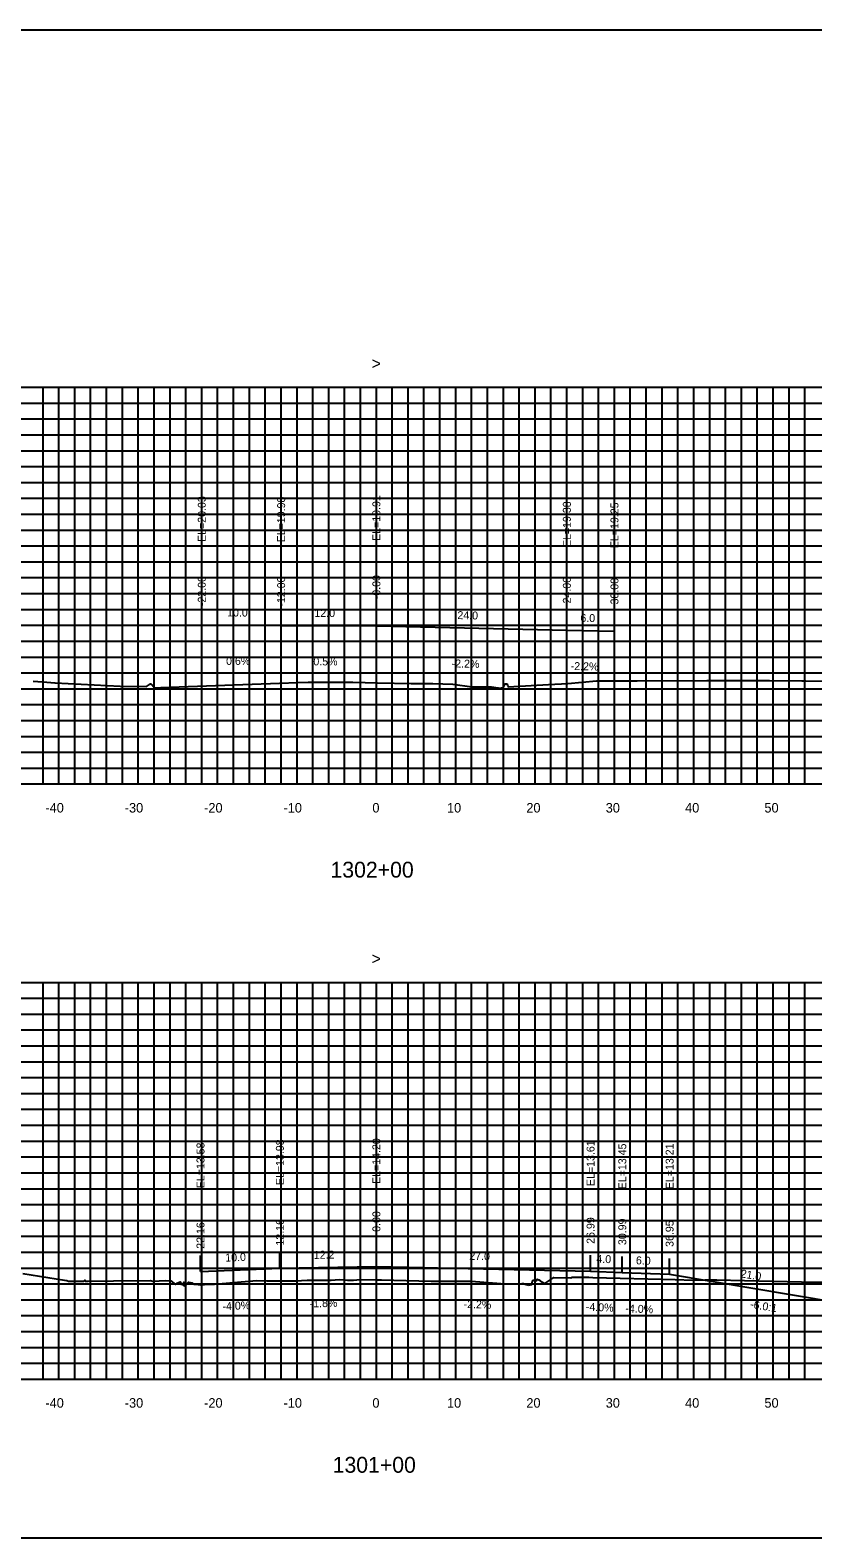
# Model space of a CAD drawing. Extents: x 1797714 to 1804825, y 249015 to 250269.
# Drawn here: x 1802560.5 to 1802659.2, y 249628.2 to 249818.2 of the extents above; entities that cross this region are included whole.
import ezdxf

# ---------------------------------------------------------------- set-up
doc = ezdxf.new("R2010")
doc.units = 0
for name, color, linetype in [('1', 7, 'Continuous'), ('10', 7, 'Continuous'), ('3', 7, 'Continuous'), ('4', 7, 'Continuous'), ('60', 7, 'Continuous'), ('CL-CNST', 7, 'Continuous'), ('Level 62', 7, 'Continuous'), ('M-ROADS', 7, 'Continuous')]:
    doc.layers.add(name, color=color, linetype=linetype)

msp = doc.modelspace()

# ---------------------------------------------------------------- linework, layer by layer
for p, q in [((1802582.16, 249743.2), (1802582.16, 249745.2)), ((1802592.16, 249743.14), (1802592.16, 249745.14)), ((1802604.16, 249743.08), (1802604.16, 249745.08)), ((1802628.16, 249742.55), (1802628.16, 249744.55)), ((1802634.16, 249742.42), (1802634.16, 249744.42)), ((1802592, 249662.14), (1802592, 249664.14)), ((1802604.16, 249662.37), (1802604.16, 249664.37)), ((1802582, 249661.74), (1802582, 249663.74)), ((1802631.15, 249661.77), (1802631.15, 249663.77)), ((1802635.15, 249661.61), (1802635.15, 249663.61)), ((1802641.11, 249661.38), (1802641.11, 249663.38))]:
    msp.add_line(p, q)
msp.add_lwpolyline([(1802454.16, 249628.17), (1802754.16, 249628.17), (1802754.16, 249818.17), (1802454.16, 249818.17)], close=True)
at = {"layer": '60'}
for p, q in [((1802454.16, 249723.17), (1802754.16, 249723.17)), ((1802564.16, 249723.11), (1802564.16, 249723.17)), ((1802574.16, 249723.11), (1802574.16, 249723.17)), ((1802584.16, 249723.11), (1802584.16, 249723.17)), ((1802594.16, 249723.11), (1802594.16, 249723.17)), ((1802604.16, 249723.11), (1802604.16, 249723.17)), ((1802614.16, 249723.11), (1802614.16, 249723.17)), ((1802624.16, 249723.11), (1802624.16, 249723.17)), ((1802634.16, 249723.11), (1802634.16, 249723.17)), ((1802644.16, 249723.11), (1802644.16, 249723.17)), ((1802654.16, 249723.11), (1802654.16, 249723.17)), ((1802454.16, 249648.17), (1802754.16, 249648.17)), ((1802564.16, 249648.11), (1802564.16, 249648.17)), ((1802574.16, 249648.11), (1802574.16, 249648.17)), ((1802584.16, 249648.11), (1802584.16, 249648.17)), ((1802594.16, 249648.11), (1802594.16, 249648.17)), ((1802604.16, 249648.11), (1802604.16, 249648.17)), ((1802614.16, 249648.11), (1802614.16, 249648.17)), ((1802624.16, 249648.11), (1802624.16, 249648.17)), ((1802634.16, 249648.11), (1802634.16, 249648.17)), ((1802644.16, 249648.11), (1802644.16, 249648.17)), ((1802654.16, 249648.11), (1802654.16, 249648.17))]:
    msp.add_line(p, q, dxfattribs=at)
at = {"layer": 'CL-CNST'}
for points in [[(1802582.16, 249743.2), (1802592.16, 249743.14), (1802604.16, 249743.08), (1802628.16, 249742.55), (1802634.16, 249742.42)], [(1802582, 249661.74), (1802592, 249662.14), (1802604.16, 249662.37), (1802631.15, 249661.77), (1802635.15, 249661.61), (1802641.11, 249661.38), (1802662.11, 249657.88), (1802666.11, 249657.88), (1802676.28, 249660.42)]]:
    msp.add_lwpolyline(points, dxfattribs=at)
at = {"layer": 'Level 62'}
for p, q in [((1802454.16, 249773.17), (1802754.16, 249773.17)), ((1802562.16, 249723.17), (1802562.16, 249773.17)), ((1802564.16, 249723.17), (1802564.16, 249773.17)), ((1802566.16, 249723.17), (1802566.16, 249773.17)), ((1802568.16, 249723.17), (1802568.16, 249773.17)), ((1802570.16, 249723.17), (1802570.16, 249773.17)), ((1802572.16, 249723.17), (1802572.16, 249773.17)), ((1802574.16, 249723.17), (1802574.16, 249773.17)), ((1802576.16, 249723.17), (1802576.16, 249773.17)), ((1802578.16, 249723.17), (1802578.16, 249773.17)), ((1802580.16, 249723.17), (1802580.16, 249773.17)), ((1802582.16, 249723.17), (1802582.16, 249773.17)), ((1802584.16, 249723.17), (1802584.16, 249773.17)), ((1802586.16, 249723.17), (1802586.16, 249773.17)), ((1802588.16, 249723.17), (1802588.16, 249773.17)), ((1802590.16, 249723.17), (1802590.16, 249773.17)), ((1802592.16, 249723.17), (1802592.16, 249773.17)), ((1802594.16, 249723.17), (1802594.16, 249773.17)), ((1802596.16, 249723.17), (1802596.16, 249773.17)), ((1802598.16, 249723.17), (1802598.16, 249773.17)), ((1802600.16, 249723.17), (1802600.16, 249773.17)), ((1802602.16, 249723.17), (1802602.16, 249773.17)), ((1802604.16, 249723.17), (1802604.16, 249773.17)), ((1802606.16, 249723.17), (1802606.16, 249773.17)), ((1802608.16, 249723.17), (1802608.16, 249773.17)), ((1802610.16, 249723.17), (1802610.16, 249773.17)), ((1802612.16, 249723.17), (1802612.16, 249773.17)), ((1802614.16, 249723.17), (1802614.16, 249773.17)), ((1802616.16, 249723.17), (1802616.16, 249773.17)), ((1802618.16, 249723.17), (1802618.16, 249773.17)), ((1802620.16, 249723.17), (1802620.16, 249773.17)), ((1802622.16, 249723.17), (1802622.16, 249773.17)), ((1802624.16, 249723.17), (1802624.16, 249773.17)), ((1802626.16, 249723.17), (1802626.16, 249773.17)), ((1802628.16, 249723.17), (1802628.16, 249773.17)), ((1802630.16, 249723.17), (1802630.16, 249773.17)), ((1802632.16, 249723.17), (1802632.16, 249773.17)), ((1802634.16, 249723.17), (1802634.16, 249773.17)), ((1802636.16, 249723.17), (1802636.16, 249773.17)), ((1802638.16, 249723.17), (1802638.16, 249773.17)), ((1802640.16, 249723.17), (1802640.16, 249773.17)), ((1802642.16, 249723.17), (1802642.16, 249773.17)), ((1802644.16, 249723.17), (1802644.16, 249773.17)), ((1802646.16, 249723.17), (1802646.16, 249773.17)), ((1802648.16, 249723.17), (1802648.16, 249773.17)), ((1802650.16, 249723.17), (1802650.16, 249773.17)), ((1802652.16, 249723.17), (1802652.16, 249773.17)), ((1802654.16, 249723.17), (1802654.16, 249773.17)), ((1802656.16, 249723.17), (1802656.16, 249773.17)), ((1802658.16, 249723.17), (1802658.16, 249773.17)), ((1802454.16, 249771.17), (1802754.16, 249771.17)), ((1802454.16, 249769.17), (1802754.16, 249769.17)), ((1802454.16, 249767.17), (1802754.16, 249767.17)), ((1802454.16, 249765.17), (1802754.16, 249765.17)), ((1802454.16, 249763.17), (1802754.16, 249763.17)), ((1802454.16, 249761.17), (1802754.16, 249761.17)), ((1802454.16, 249759.17), (1802754.16, 249759.17)), ((1802454.16, 249757.17), (1802754.16, 249757.17)), ((1802454.16, 249755.17), (1802754.16, 249755.17)), ((1802454.16, 249753.17), (1802754.16, 249753.17)), ((1802454.16, 249751.17), (1802754.16, 249751.17)), ((1802454.16, 249749.17), (1802754.16, 249749.17)), ((1802454.16, 249747.17), (1802754.16, 249747.17)), ((1802454.16, 249745.17), (1802754.16, 249745.17)), ((1802454.16, 249743.17), (1802754.16, 249743.17)), ((1802454.16, 249741.17), (1802754.16, 249741.17)), ((1802454.16, 249739.17), (1802754.16, 249739.17)), ((1802454.16, 249737.17), (1802754.16, 249737.17)), ((1802454.16, 249735.17), (1802754.16, 249735.17)), ((1802454.16, 249733.17), (1802754.16, 249733.17)), ((1802454.16, 249731.17), (1802754.16, 249731.17)), ((1802454.16, 249729.17), (1802754.16, 249729.17)), ((1802454.16, 249727.17), (1802754.16, 249727.17)), ((1802454.16, 249725.17), (1802754.16, 249725.17)), ((1802454.16, 249723.17), (1802754.16, 249723.17)), ((1802454.16, 249698.17), (1802754.16, 249698.17)), ((1802562.16, 249648.17), (1802562.16, 249698.17)), ((1802564.16, 249648.17), (1802564.16, 249698.17)), ((1802566.16, 249648.17), (1802566.16, 249698.17)), ((1802568.16, 249648.17), (1802568.16, 249698.17)), ((1802570.16, 249648.17), (1802570.16, 249698.17)), ((1802572.16, 249648.17), (1802572.16, 249698.17)), ((1802574.16, 249648.17), (1802574.16, 249698.17)), ((1802576.16, 249648.17), (1802576.16, 249698.17)), ((1802578.16, 249648.17), (1802578.16, 249698.17)), ((1802580.16, 249648.17), (1802580.16, 249698.17)), ((1802582.16, 249648.17), (1802582.16, 249698.17)), ((1802584.16, 249648.17), (1802584.16, 249698.17)), ((1802586.16, 249648.17), (1802586.16, 249698.17)), ((1802588.16, 249648.17), (1802588.16, 249698.17)), ((1802590.16, 249648.17), (1802590.16, 249698.17)), ((1802592.16, 249648.17), (1802592.16, 249698.17)), ((1802594.16, 249648.17), (1802594.16, 249698.17)), ((1802596.16, 249648.17), (1802596.16, 249698.17)), ((1802598.16, 249648.17), (1802598.16, 249698.17)), ((1802600.16, 249648.17), (1802600.16, 249698.17)), ((1802602.16, 249648.17), (1802602.16, 249698.17)), ((1802604.16, 249648.17), (1802604.16, 249698.17)), ((1802606.16, 249648.17), (1802606.16, 249698.17)), ((1802608.16, 249648.17), (1802608.16, 249698.17)), ((1802610.16, 249648.17), (1802610.16, 249698.17)), ((1802612.16, 249648.17), (1802612.16, 249698.17)), ((1802614.16, 249648.17), (1802614.16, 249698.17)), ((1802616.16, 249648.17), (1802616.16, 249698.17)), ((1802618.16, 249648.17), (1802618.16, 249698.17)), ((1802620.16, 249648.17), (1802620.16, 249698.17)), ((1802622.16, 249648.17), (1802622.16, 249698.17)), ((1802624.16, 249648.17), (1802624.16, 249698.17)), ((1802626.16, 249648.17), (1802626.16, 249698.17)), ((1802628.16, 249648.17), (1802628.16, 249698.17)), ((1802630.16, 249648.17), (1802630.16, 249698.17)), ((1802632.16, 249648.17), (1802632.16, 249698.17)), ((1802634.16, 249648.17), (1802634.16, 249698.17)), ((1802636.16, 249648.17), (1802636.16, 249698.17)), ((1802638.16, 249648.17), (1802638.16, 249698.17)), ((1802640.16, 249648.17), (1802640.16, 249698.17)), ((1802642.16, 249648.17), (1802642.16, 249698.17)), ((1802644.16, 249648.17), (1802644.16, 249698.17)), ((1802646.16, 249648.17), (1802646.16, 249698.17)), ((1802648.16, 249648.17), (1802648.16, 249698.17)), ((1802650.16, 249648.17), (1802650.16, 249698.17)), ((1802652.16, 249648.17), (1802652.16, 249698.17)), ((1802654.16, 249648.17), (1802654.16, 249698.17)), ((1802656.16, 249648.17), (1802656.16, 249698.17)), ((1802658.16, 249648.17), (1802658.16, 249698.17)), ((1802454.16, 249696.17), (1802754.16, 249696.17)), ((1802454.16, 249694.17), (1802754.16, 249694.17)), ((1802454.16, 249692.17), (1802754.16, 249692.17)), ((1802454.16, 249690.17), (1802754.16, 249690.17)), ((1802454.16, 249688.17), (1802754.16, 249688.17)), ((1802454.16, 249686.17), (1802754.16, 249686.17)), ((1802454.16, 249684.17), (1802754.16, 249684.17)), ((1802454.16, 249682.17), (1802754.16, 249682.17)), ((1802454.16, 249680.17), (1802754.16, 249680.17)), ((1802454.16, 249678.17), (1802754.16, 249678.17)), ((1802454.16, 249676.17), (1802754.16, 249676.17)), ((1802454.16, 249674.17), (1802754.16, 249674.17)), ((1802454.16, 249672.17), (1802754.16, 249672.17)), ((1802454.16, 249670.17), (1802754.16, 249670.17)), ((1802454.16, 249668.17), (1802754.16, 249668.17)), ((1802454.16, 249666.17), (1802754.16, 249666.17)), ((1802454.16, 249664.17), (1802754.16, 249664.17)), ((1802454.16, 249662.17), (1802754.16, 249662.17)), ((1802454.16, 249660.17), (1802754.16, 249660.17)), ((1802454.16, 249658.17), (1802754.16, 249658.17)), ((1802454.16, 249656.17), (1802754.16, 249656.17)), ((1802454.16, 249654.17), (1802754.16, 249654.17)), ((1802454.16, 249652.17), (1802754.16, 249652.17)), ((1802454.16, 249650.17), (1802754.16, 249650.17)), ((1802454.16, 249648.17), (1802754.16, 249648.17))]:
    msp.add_line(p, q, dxfattribs=at)
at = {"layer": 'M-ROADS'}
for points in [[(1802560.91, 249736.14), (1802562.64, 249735.99), (1802563.66, 249735.9), (1802563.68, 249735.93), (1802571.88, 249735.49), (1802575.19, 249735.45), (1802575.72, 249735.8), (1802575.98, 249735.55), (1802576.22, 249735.3), (1802576.99, 249735.31), (1802591.97, 249735.86), (1802594.27, 249735.97), (1802595.55, 249735.99), (1802596.23, 249736.01), (1802597.8, 249736.01), (1802598.5, 249736.01), (1802598.62, 249736.01), (1802598.86, 249736.02), (1802600.31, 249736.01), (1802601.2, 249736.01), (1802604.3, 249735.93), (1802608.54, 249735.85), (1802609.58, 249735.85), (1802611.28, 249735.85), (1802613.79, 249735.74), (1802616.19, 249735.42), (1802616.84, 249735.42), (1802618.25, 249735.42), (1802618.28, 249735.42), (1802618.3, 249735.42), (1802618.66, 249735.41), (1802619.5, 249735.27), (1802619.54, 249735.27), (1802619.8, 249735.26), (1802619.92, 249735.29), (1802620.13, 249735.3), (1802620.15, 249735.28), (1802620.29, 249735.61), (1802620.36, 249735.77), (1802620.39, 249735.77), (1802620.49, 249735.77), (1802620.64, 249735.77), (1802620.7, 249735.56), (1802620.72, 249735.52), (1802620.75, 249735.48), (1802620.78, 249735.42), (1802625.84, 249735.71), (1802628.3, 249735.84), (1802631.88, 249736.17), (1802631.97, 249736.17), (1802632.32, 249736.17), (1802634.58, 249736.17), (1802634.64, 249736.17), (1802637.03, 249736.17), (1802645.82, 249736.22), (1802645.95, 249736.22), (1802646.32, 249736.22), (1802653.7, 249736.2), (1802657.76, 249736.16), (1802657.91, 249736.16), (1802658.26, 249736.16), (1802662.86, 249736.12)], [(1802559.63, 249661.47), (1802564.86, 249660.66), (1802565.16, 249660.61), (1802565.35, 249660.53), (1802565.99, 249660.52), (1802566.38, 249660.51), (1802567.13, 249660.5), (1802567.3, 249660.52), (1802567.42, 249660.66), (1802567.48, 249660.51), (1802567.84, 249660.52), (1802571.03, 249660.57), (1802575.72, 249660.61), (1802576, 249660.52), (1802577.6, 249660.61), (1802578.2, 249660.57), (1802578.27, 249660.57), (1802578.8, 249660.13), (1802578.84, 249660.14), (1802578.92, 249660.19), (1802578.97, 249660.22), (1802579.02, 249660.27), (1802579.05, 249660.27), (1802579.08, 249660.26), (1802579.14, 249660.28), (1802579.16, 249660.3), (1802579.17, 249660.3), (1802579.19, 249660.32), (1802579.2, 249660.33), (1802579.22, 249660.35), (1802579.23, 249660.35), (1802579.24, 249660.36), (1802579.42, 249660.45), (1802579.56, 249660.15), (1802579.58, 249660.12), (1802579.84, 249660.07), (1802579.9, 249660.01), (1802579.9, 249659.99), (1802579.91, 249660.37), (1802579.92, 249659.97), (1802579.98, 249659.92), (1802580.09, 249659.98), (1802580.49, 249660.37), (1802580.91, 249660.29), (1802581.16, 249660.13), (1802581.42, 249660.15), (1802582.01, 249660.06), (1802583, 249660.15), (1802583.77, 249660.14), (1802585.68, 249660.31), (1802589.06, 249660.58), (1802590.35, 249660.57), (1802591.37, 249660.57), (1802591.54, 249660.57), (1802591.72, 249660.57), (1802592.8, 249660.57), (1802594.03, 249660.57), (1802595.44, 249660.63), (1802596.27, 249660.64), (1802598.39, 249660.64), (1802598.48, 249660.64), (1802599.46, 249660.71), (1802600.53, 249660.65), (1802600.98, 249660.64), (1802601.29, 249660.66), (1802601.71, 249660.68), (1802602.02, 249660.71), (1802604.3, 249660.7), (1802604.43, 249660.7), (1802604.79, 249660.69), (1802611.07, 249660.52), (1802613.22, 249660.51), (1802613.3, 249660.51), (1802613.31, 249660.51), (1802613.65, 249660.53), (1802615.72, 249660.53), (1802616.05, 249660.53), (1802616.67, 249660.48), (1802620.38, 249660.19), (1802622.47, 249660.23), (1802622.71, 249660.23), (1802623.03, 249660.08), (1802623.16, 249660.03), (1802623.24, 249660.08), (1802623.37, 249660), (1802623.39, 249660.01), (1802623.75, 249660.11), (1802623.8, 249660.28), (1802623.82, 249660.56), (1802623.93, 249660.64), (1802623.94, 249660.64), (1802624.14, 249660.62), (1802624.29, 249660.6), (1802624.32, 249660.56), (1802624.33, 249660.57), (1802624.41, 249660.72), (1802624.44, 249660.77), (1802624.64, 249660.67), (1802624.78, 249660.57), (1802625.37, 249660.2), (1802626.4, 249660.89), (1802626.54, 249660.98), (1802628.65, 249660.94), (1802628.84, 249661), (1802629.31, 249661), (1802630.95, 249661), (1802631.42, 249660.99), (1802641.81, 249660.72), (1802644.02, 249660.65), (1802645.55, 249660.68), (1802646.33, 249660.68), (1802646.5, 249660.68), (1802647.07, 249660.68), (1802650.54, 249660.61), (1802657.73, 249660.41), (1802658.5, 249660.4), (1802660.39, 249660.43)]]:
    msp.add_lwpolyline(points, dxfattribs=at)

# ---------------------------------------------------------------- texts
msp.add_text('-6.0:1', height=1, rotation=350.5377).set_placement((1802651.2, 249657.16))
at = {"layer": '1'}
for s, p in [('1302+00', (1802598.38, 249711.37)), ('1301+00', (1802598.65, 249636.37))]:
    msp.add_text(s, height=2, dxfattribs=at).set_placement(p)
at = {"layer": '10'}
for s, p in [('-40', (1802562.46, 249719.57)), ('-30', (1802572.46, 249719.57)), ('-20', (1802582.46, 249719.57)), ('-10', (1802592.46, 249719.57)), ('0', (1802603.66, 249719.57)), ('10', (1802613.06, 249719.57)), ('20', (1802623.06, 249719.57)), ('30', (1802633.06, 249719.57)), ('40', (1802643.06, 249719.57)), ('50', (1802653.06, 249719.57)), ('-40', (1802562.46, 249644.57)), ('-30', (1802572.46, 249644.57)), ('-20', (1802582.46, 249644.57)), ('-10', (1802592.46, 249644.57)), ('0', (1802603.66, 249644.57)), ('10', (1802613.06, 249644.57)), ('20', (1802623.06, 249644.57)), ('30', (1802633.06, 249644.57)), ('40', (1802643.06, 249644.57)), ('50', (1802653.06, 249644.57))]:
    msp.add_text(s, height=1.2, dxfattribs=at).set_placement(p)
at = {"layer": '3'}
for s, p in [('EL=20.03', (1802582.66, 249753.67)), ('EL=19.98', (1802592.66, 249753.62)), ('EL=19.91', (1802604.66, 249753.8)), ('EL=19.38', (1802628.66, 249753.02)), ('EL=19.25', (1802634.66, 249752.89)), ('-22.00', (1802582.66, 249745.58)), ('-0.00', (1802604.66, 249746.45)), ('-12.00', (1802592.66, 249745.52)), ('24.00', (1802628.66, 249745.92)), ('30.00', (1802634.66, 249745.79)), ('EL=13.58', (1802582.5, 249672.22)), ('EL=13.98', (1802592.5, 249672.62)), ('EL=14.20', (1802604.66, 249672.76)), ('EL=13.61', (1802631.65, 249672.5)), ('EL=13.45', (1802635.65, 249672.09)), ('EL=13.21', (1802641.61, 249672.1)), ('-22.16', (1802582.5, 249664.15)), ('-12.16', (1802592.5, 249664.55)), ('0.00', (1802604.66, 249666.73)), ('26.99', (1802631.65, 249665.22)), ('30.99', (1802635.65, 249665.06)), ('36.95', (1802641.61, 249664.83))]:
    msp.add_text(s, height=1, rotation=90, dxfattribs=at).set_placement(p)
at = {"layer": '4'}
for s, rotation, p in [('10.0', 359.6849, (1802585.35, 249744.28)), ('12.0', 359.6849, (1802596.35, 249744.22)), ('24.0', 358.7397, (1802614.36, 249743.95)), ('6.0', 358.7397, (1802629.86, 249743.61)), ('0.6%', 359.6849, (1802585.22, 249738.18)), ('0.5%', 359.6849, (1802596.22, 249738.12)), ('-2.2%', 358.7397, (1802613.64, 249737.87)), ('-2.2%', 358.7397, (1802628.64, 249737.54)), ('10.0', 2.2906, (1802585.14, 249662.97)), ('12.2', 1.0549, (1802596.28, 249663.32)), ('27.0', 358.7397, (1802615.86, 249663.21)), ('4.0', 357.7094, (1802631.87, 249662.85)), ('6.0', 357.7094, (1802636.85, 249662.65)), ('21.0', 350.5377, (1802650, 249661.01)), ('-1.8%', 1.0549, (1802595.76, 249657.21)), ('-2.2%', 358.7397, (1802615.14, 249657.13)), ('-4.0%', 2.2906, (1802584.79, 249656.85)), ('-4.0%', 357.7094, (1802630.54, 249656.8)), ('-4.0%', 357.7094, (1802635.52, 249656.6))]:
    msp.add_text(s, height=1, rotation=rotation, dxfattribs=at).set_placement(p)
at = {"layer": '60'}
for p in [(1802603.55, 249775.42), (1802603.55, 249700.42)]:
    msp.add_text('>', height=1.5, dxfattribs=at).set_placement(p)

doc.saveas('drawing.dxf')
